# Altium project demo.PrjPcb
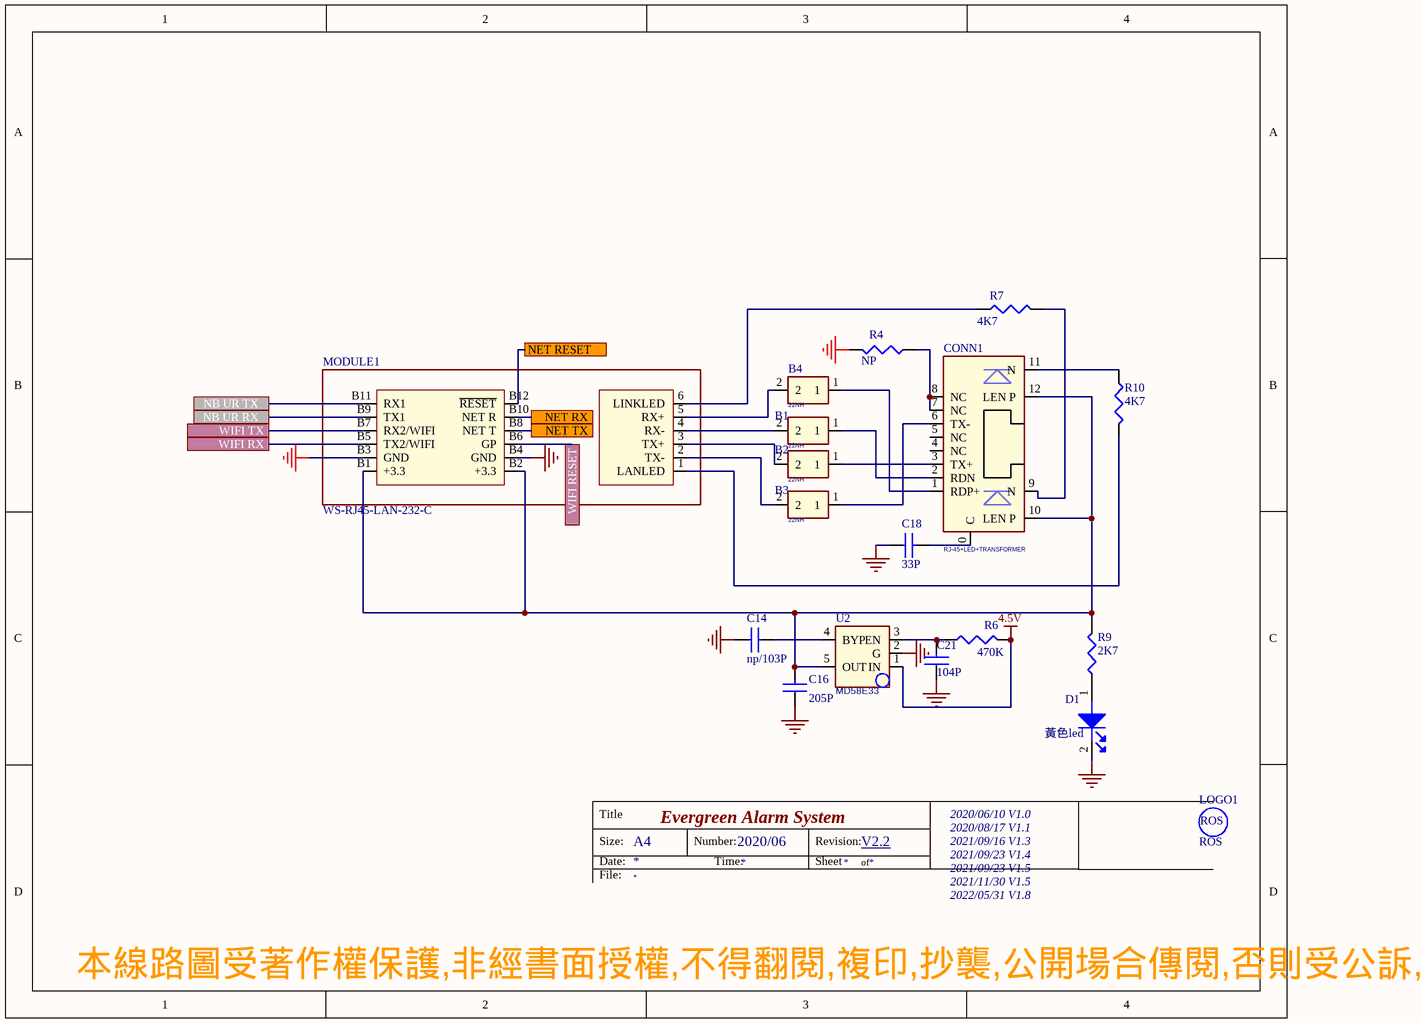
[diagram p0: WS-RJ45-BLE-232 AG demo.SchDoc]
1 sheet, 19 parts. Net scope: flat (ports and power ports of the same name join across sheets).
Board file: WS-RJ45-BLE-232 AG demo.PcbDoc

## Sheet WS-RJ45-BLE-232 AG demo.SchDoc: 停車TAG 2.425GHZ
size A; DrawnBy: ANDYLIN; Engineer: ANDYLIN; Address1: 2017/11/25; Address2: 12/7 修正零件參數; Address3: 12/25修改中斷輸入 i/o; Address4: 1/3量產; DocumentNumber: 201711; Revision: V3

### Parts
*3  LOG WS  [LOG WS]  (value not drawn)
B1  22NH  [B0402]
B2  22NH  [B0402]
B3  22NH  [B0402]
B4  22NH  [B0402]
C14  np/103P  [CAP0402]
C16  205P  [CAP0402]
C18  33P  [CAP0402]
C21  104P  [CAP0402]
CONN1  RJ-45+LED+TRANSFORMER  [RJ45-led - 90]
D1  黃色led  [LED 0603_GREEN]
LOGO1  ROS  [PB]
MODULE1  WS-RJ45-LAN-232-C  [WS-RJ45-LAN-232-C -HC]
R4  NP  [R0402]
R6  470K  [R0402]
R7  4K7  [R0402]
R9  2K7  [R0402]
R10  4K7  [R0402]
U2  MD58E33  [SOT23-5]

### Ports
NB UR RX, NB UR TX, NET RESET, NET RX, NET TX, WIFI RESET, WIFI RX, WIFI TX

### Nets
4.5V: R6.2 U2.1(IN)
GND: C14.2 C16.1 C18.1 C21.1 D1.2(CATHODE) MODULE1.B3(GND) MODULE1.B4(GND) R4.2 U2.2(G)
NetB1_1: B1.1 CONN1.2(RDN)
NetB1_2: B1.2 MODULE1.4(RX-)
NetB2_1: B2.1 CONN1.3(TX+)
NetB2_2: B2.2 MODULE1.3(TX+)
NetB3_1: B3.1 CONN1.6(TX-)
NetB3_2: B3.2 MODULE1.2(TX-)
NetB4_1: B4.1 CONN1.1(RDP+)
NetB4_2: B4.2 MODULE1.5(RX+)
NetC14_1: C14.1 U2.4(BYP)
NetC16_2: C16.2 CONN1.10(LEN_P) CONN1.12(LEN_P) MODULE1.B1(+3.3) MODULE1.B2(+3.3) R9.1 U2.5(OUT)
NetC18_2: C18.2 CONN1.0(C)
NetC21_2: C21.2 R6.1 U2.3(EN)
NetCONN1_7: CONN1.7(NC) CONN1.8(NC) R4.1
NetCONN1_9: CONN1.9(N) R7.2
NetCONN1_11: CONN1.11(N) R10.1
NetD1_1: D1.1(ANODE) R9.2
NetMODULE1_1: MODULE1.1(LANLED) R10.2
NetMODULE1_6: MODULE1.6(LINKLED) R7.1
NetMODULE1_B5: MODULE1.B5(TX2/WIFI) ; port WIFI RX
NetMODULE1_B6: MODULE1.B6(GP) ; port WIFI RESET
NetMODULE1_B7: MODULE1.B7(RX2/WIFI) ; port WIFI TX
NetMODULE1_B8: MODULE1.B8(NET_T) ; port NET TX
NetMODULE1_B9: MODULE1.B9(TX1) ; port NB UR RX
NetMODULE1_B10: MODULE1.B10(NET_R) ; port NET RX
NetMODULE1_B11: MODULE1.B11(RX1) ; port NB UR TX
NetMODULE1_B12: MODULE1.B12(~{RESET}) ; port NET RESET

Not connected (* = marked no-connect by the designer): CONN1 4(NC) 5(NC)

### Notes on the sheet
- Title
- Evergreen Alarm System
- 2020/06/10 V1.0
- 2020/08/17 V1.1
- Size:
- Date:
- File:
- A4
- Number:
- Time:
- 2020/06
- Revision:
- Sheet
- V2.2 <RF.NET.TW>
- of
- 2021/09/16 V1.3
- 2021/09/23 V1.4
- 2021/09/23 V1.5
- 2021/11/30 V1.5
- 2022/05/31 V1.8
- 本線路圖受著作權保護,非經書面授權,不得翻閱,複印,抄襲,公開場合傳閱,否則受公訴,民事責任及公司法

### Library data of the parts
B1-B4 = BEAD
C14 C16 C18 C21 = CAP NP
CONN1 = RJ-45
D1 = LED
MODULE1 = WS-RJ45-LAN-232-C: WENSHING ELECTRO MODULE
R4 R6 R7 R9 R10 = R
U2 = MIC5219-3.3BM5: 封裝: SOT-23-5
